// Mitsubishi GX Works2 project: code_plc_misu_nangsuat   PLC: FX1S

PROGRAM MAIN
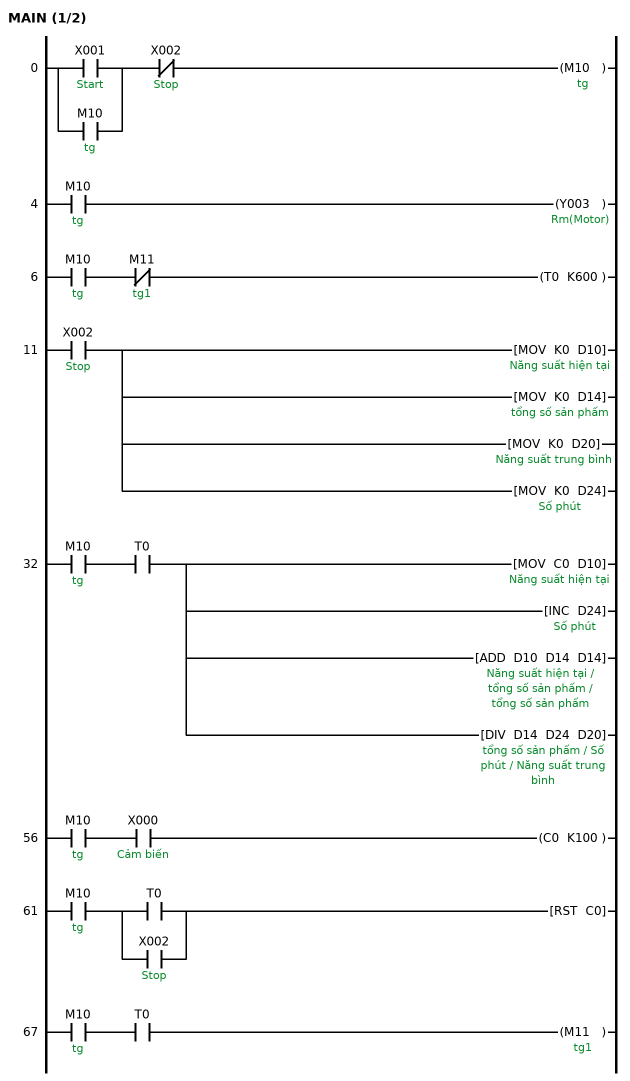
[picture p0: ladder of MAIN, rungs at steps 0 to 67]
0     LD      X001  ; Start
      OR      M10  ; tg
      ANI     X002  ; Stop
      OUT     M10  ; tg
4     LD      M10  ; tg
      OUT     Y003  ; Rm(Motor)
6     LD      M10  ; tg
      ANI     M11  ; tg1
      OUT     T0 K600
11    LD      X002  ; Stop
      MOV     K0 D10  ; Năng suất hiện tại
      MOV     K0 D14  ; tổng số sản phấm
      MOV     K0 D20  ; Năng suất trung bình
      MOV     K0 D24  ; Số phút
32    LD      M10  ; tg
      AND     T0
      MOV     C0 D10
      INC     D24
      ADD     D10 D14 D14
      DIV     D14 D24 D20
56    LD      M10  ; tg
      AND     X000  ; Cảm biến
      OUT     C0 K100
61    LD      M10  ; tg
      LD      T0
      OR      X002  ; Stop
      ANB
      RST     C0
67    LD      M10  ; tg
      AND     T0
      OUT     M11  ; tg1
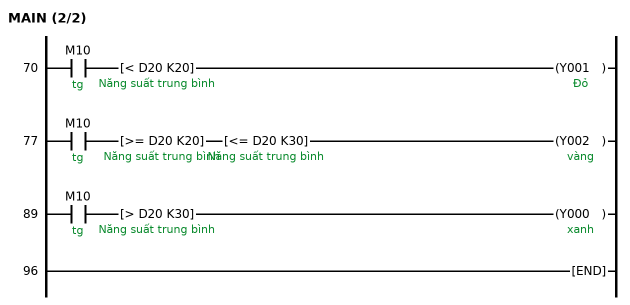
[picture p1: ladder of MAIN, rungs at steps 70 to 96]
70    LD      M10  ; tg
      AND<    D20 K20  ; Năng suất trung bình
      OUT     Y001  ; Đỏ
77    LD      M10  ; tg
      AND>=   D20 K20  ; Năng suất trung bình
      AND<=   D20 K30  ; Năng suất trung bình
      OUT     Y002  ; vàng
89    LD      M10  ; tg
      AND>    D20 K30  ; Năng suất trung bình
      OUT     Y000  ; xanh
96    END
END_PROGRAM
